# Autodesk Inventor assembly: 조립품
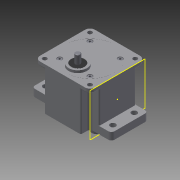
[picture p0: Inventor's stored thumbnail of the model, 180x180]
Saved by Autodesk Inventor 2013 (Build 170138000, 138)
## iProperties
Created: 2015-07
Part Number: 조립품
Document SubType Name: Assembly
Designer: user
Author: user
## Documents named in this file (12)
- C:\Users\user\Desktop\450734V1017\조립품.iam
- C:\Users\user\Desktop\본체.ipt
- C:\Users\user\Desktop\450734V1017\커버.ipt
- C:\Users\user\Desktop\450734V1017\서브축.ipt
- C:\Users\user\Desktop\450734V1017\베어링 608.ipt
- 베어링 608.ipt
- C:\Users\user\Desktop\450734V1017\베어링 6003.ipt
- 베어링 6003.ipt
- C:\Users\user\Desktop\450734V1017\메인축.ipt
- C:\Users\user\Desktop\450734V1017\오일실 17x32x8.ipt
- C:\Users\user\Desktop\450734V1017\오일실 8x22x7.ipt
- C:\Users\user\Desktop\450734V1017\M4x0.5x16.ipt
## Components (4 placed, 1 different names)
1. M4x0.5x12:1
2. M4x0.5x12:2
3. M4x0.5x12:3
4. M4x0.5x12:4
